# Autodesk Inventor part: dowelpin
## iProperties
Author: cdotson
Shininess: 20.0
PropertySet Name: _Private Model Information
Created: 2001-01
Part Number: dowelpin
Document SubType Name: Modeling
Designer: cdotson
Description: Dowel Pin, Production
Control State: 0
Master: False
Checked Out: False
PropertySet Name: Design Tracking Control
Density: 0.0
Volumn: 0.0
Area: 0.0
PropertySet Name: Model Information
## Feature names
1. Extrusion1
2. Fillet1
